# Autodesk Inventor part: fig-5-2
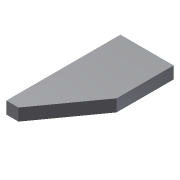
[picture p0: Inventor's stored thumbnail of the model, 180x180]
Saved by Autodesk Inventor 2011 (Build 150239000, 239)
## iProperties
Shininess: 64.0
Length Units: 11272
Angle Units: 11279
Time Units: 11290
Mass Units: 11283
Length Display Precision: 3
Angle Display Precision: 2
Compacted: True
Part Number: fig-5-2
Document SubType Name: Modeling
Created: 2003-01
Designer: Owner
Density: 1 g/cm^3
Density: 0.0
Volumn: 0.0
Area: 0.0
PropertySet Name: Model Information
Control State: 0
Master: False
Checked Out: False
Author: Owner
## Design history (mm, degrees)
sketch "Sketch1"
  geometry: L1 (-795.488, 2648.57)-(-795.488, 3054.97); L2 (1109.512, 1276.97)-(-795.488, 2648.57); L3 (3014.512, 1276.97)-(1109.512, 1276.97); L4 (3014.512, 3054.97)-(3014.512, 1276.97); L5 (-795.488, 3054.97)-(3014.512, 3054.97)
  constraints: 10 end point, 2 horizontal, 2 vertical, 1 other
  dimensions: "d1" = 3810 distance of L1.end L4.start; "d3" = 1778 distance of L4.start L3.start; "d5" = 1905 distance of L3.start L2.start; "d7" = 406.4 distance of L1.start L1.end
extrude "ExtrusionBlind1" new body sketch "Sketch1" distance "d8" = 406.4; taper "d9" = 0 deg
body "Solid1"
other parameters: "d2" = 1778 (derived), "d4" = 1905 (derived), "d6" = 406.4 (derived), "d12" = 0 (derived), "d15" = 635 (derived), "d22" = 889 (derived), "d24" = 812.8 (derived), "d26" = 711.2 (derived), "d28" = 914.4 (derived), "d34" = 812.8 (derived), "d36" = 406.4 (derived)
